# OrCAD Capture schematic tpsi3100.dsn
size B
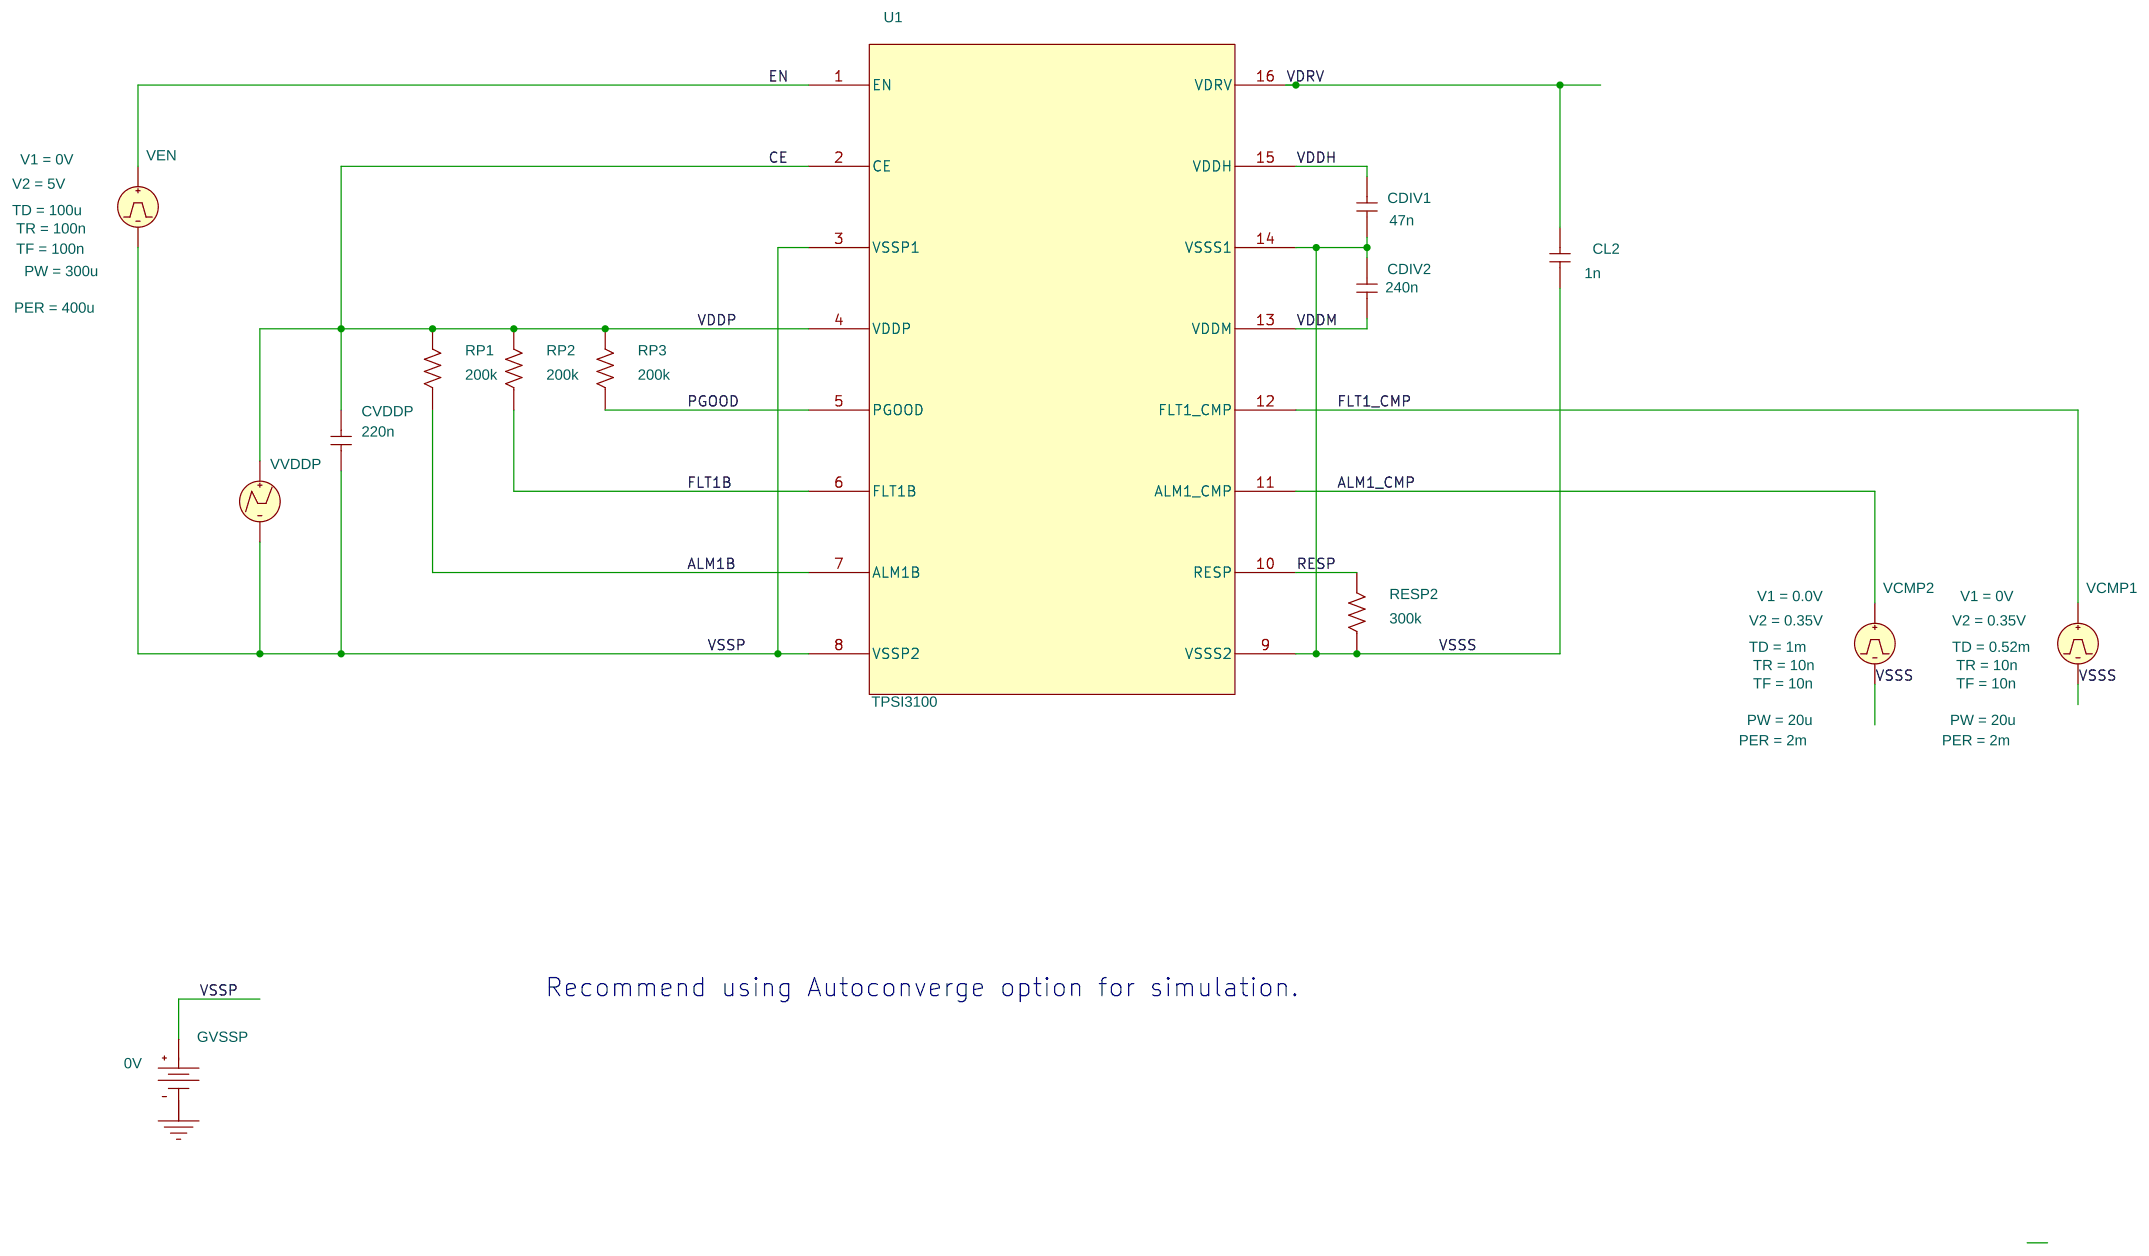
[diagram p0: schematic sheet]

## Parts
CDIV1  47n  [cap196]
CDIV2  240n  [cap196]
CL2  1n  [cap196]
CVDDP  220n  [cap196]
GVSSP  VDC
RESP2  300k  [AXRC05]
RP1  200k  [AXRC05]
RP2  200k  [AXRC05]
RP3  200k  [AXRC05]
U1  TPSI3100
VCMP1  VPULSE
VCMP2  VPULSE
VEN  VPULSE
VVDDP  VPWL

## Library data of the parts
CDIV1 CDIV2 CL2 CVDDP = C
GVSSP = VDC: DC: 0V
RESP2 RP1-RP3 = R
U1 = TPSI3100
VCMP1 = VPULSE: PER: 2m; PW: 20u; TD: 0.52m; TF: 10n; TR: 10n; V1: 0V; V2: 0.35V
VCMP2 = VPULSE: PER: 2m; PW: 20u; TD: 1m; TF: 10n; TR: 10n; V1: 0.0V; V2: 0.35V
VEN = VPULSE: PER: 400u; PW: 300u; TD: 100u; TF: 100n; TR: 100n; V1: 0V; V2: 5V
VVDDP = VPWL: T1: 0us; T2: 5us; T3: 10us; T4: 950us; T5: 1100us; V1: 0V; V2: 0V; V3: 5V; V4: 5V; V5: 5V

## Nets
VDDH: CDIV1.2 U1.15(VDDH)
VDDM: CDIV2.1 U1.13(VDDM)
VSSP: CVDDP.1 GVSSP.0(+) U1.3(VSSP1) U1.8(VSSP2) VEN.2(-) VVDDP.2(-)
VSSS: CDIV1.1 CDIV2.2 CL2.1 RESP2.1 U1.9(VSSS2) U1.14(VSSS1) VCMP1.2(-) VCMP2.2(-)
0: GVSSP.1(-)
ALM1_CMP: U1.11(ALM1_CMP) VCMP2.1(+)
ALM1B: RP1.1 U1.7(ALM1B)
CE: CVDDP.2 RP1.2 RP2.2 RP3.2 U1.2(CE) U1.4(VDDP) VVDDP.1(+)
EN: U1.1(EN) VEN.1(+)
FLT1_CMP: U1.12(FLT1_CMP) VCMP1.1(+)
FLT1B: RP2.1 U1.6(FLT1B)
PGOOD: RP3.1 U1.5(PGOOD)
RESP: RESP2.2 U1.10(RESP)
VDRV: CL2.2 U1.16(VDRV)

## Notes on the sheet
- Recommend using Autoconverge option for simulation.
